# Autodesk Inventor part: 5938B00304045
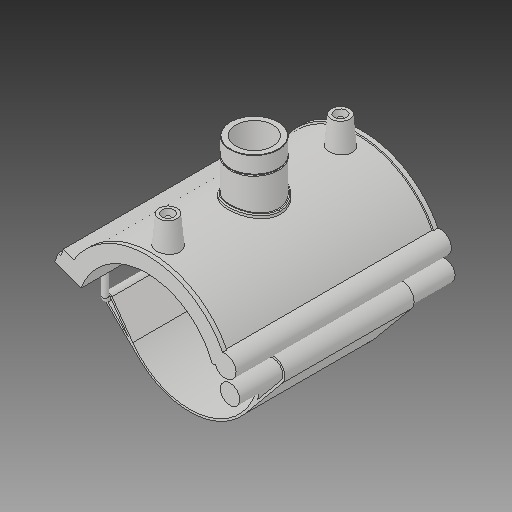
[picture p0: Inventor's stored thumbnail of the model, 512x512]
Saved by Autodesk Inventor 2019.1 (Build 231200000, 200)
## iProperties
Created: 2017-07
Part Number: 5938B00304045
Material: Generic
Description: PLASSON TRANSITION SADDLE 4''IPS x 1"NPT
Document SubType Name: Modeling
Designer: KIM
Density: 1 g/cm^3
Appearance: Default
Author: KIM
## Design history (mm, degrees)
derived "5938B.ipt"
feature "Solid1::5938B.ipt"
tag "TaggingFeature1"
body "Solid1"
other parameters: "d_" = 114.1, "B_" = 156.21, "H_" = 41.91, "L_" = 176.022, "d_t" = 6, "G_" = 30.291, "d148" = 1.7115, "d160" = 1.7115, "d169" = 1.7115, "d192" = 4.564, "d0" = 114.1, "d1" = 136.92, "d2" = 390.525, "d3" = 28.525, "d4" = 176.022, "d5" = 0, "d40" = 71.1984, "d41" = 42.4074, "d43" = 0, "d45" = 0, "d47" = 110.37, "d48" = 39.3783, "d50" = 0, "d78" = 90.46, "d79" = 15, "d80" = 70.4088, "d82" = 5 deg, "d84" = 4, "d85" = 14, "d86" = 0, "d87" = 3, "d88" = 0, "d96" = 139.6584, "d97" = 3.52044, "d98" = 0, "d102" = 0.90873, "d103" = 30.291, "d104" = 25.146, "d105" = 0, "d106" = 24.2328, "d108" = 0, "d109" = -13.97, "d111" = 0.5, "d112" = 0.5, "d113" = 0, "d114" = 0.5, "d117" = 0.30291, "d120" = 140 deg, "d121" = 24.228, "d122" = 20 deg, "d123" = 547.68, "d124" = 82.152, "d126" = 0, "d143" = 117.523, "d145" = 17.55385, "d149" = 1.7115, "d150" = 19.30923, "d153" = 176.022, "d154" = 0, "d156" = 68.46, "d157" = 160 deg, "d159" = 4.564, "d161" = 1.7115, "d162" = 105.6132, "d163" = 0, "d164" = 57.05, "d167" = 11.41, "d168" = 66.79024, "d170" = 1.7115, "d172" = 0, "d173" = 1, "d175" = 57.05, "d176" = 20 deg, "d177" = 7.987, "d178" = 22.82, "d180" = 0, "d183" = 9.128, "d184" = 6.3896, "d185" = 57.20715, "d186" = 57.20715, "d187" = 68.46, "d188" = 6.846, "d189" = 7.987, "d190" = 0, "d191" = 82.152, "d193" = 4.564, "d194" = 2.33905, "d195" = 90 deg, "d197" = 0, "d199" = 0
